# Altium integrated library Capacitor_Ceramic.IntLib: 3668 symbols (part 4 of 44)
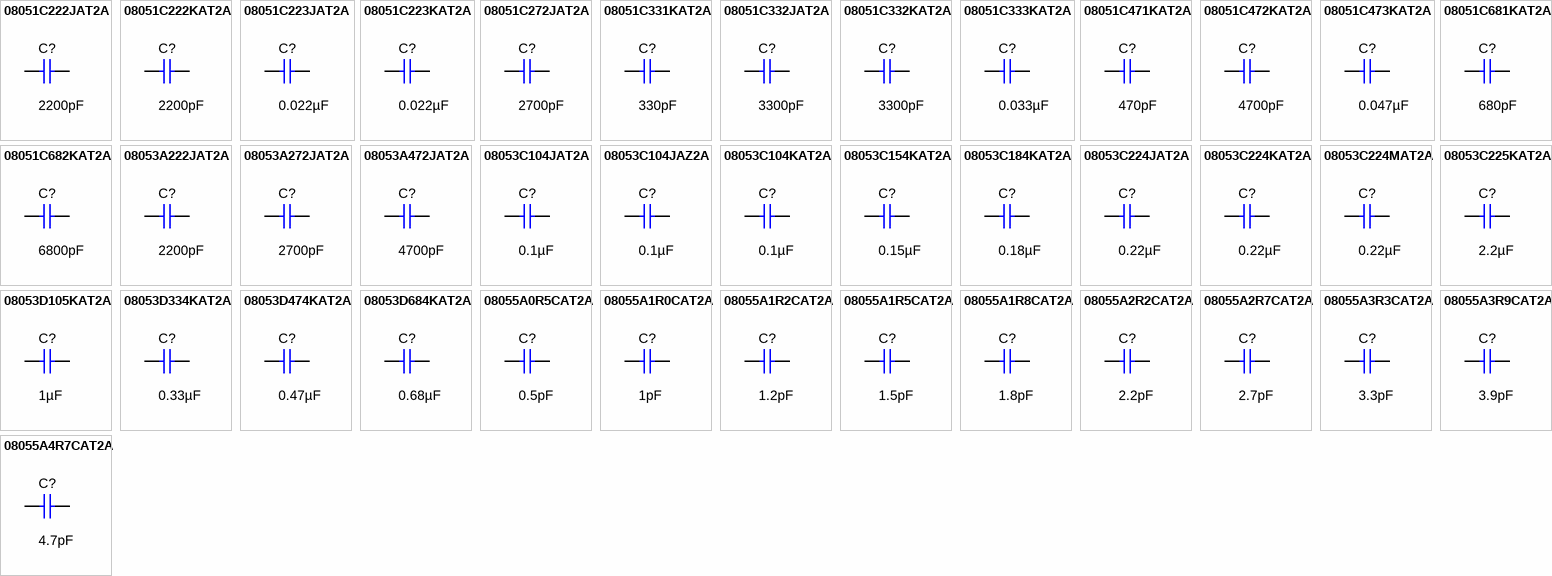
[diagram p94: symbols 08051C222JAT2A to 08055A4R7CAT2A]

## 08055A4R7CAT2A
designator C?  ValueDisplayed: 4.7pF  (hidden comment: 08055A4R7CAT2A)
CAP, CERM, 4.7 pF, 50 V,+/- 5%, C0G/NP0, 0805; Manufacturer: AVX; Polarized: N; CompType: Capacitor; Value: 4.7pF; U/M: EA; Cap_F: 0.0000000000047; Tolerance_%: 5; ESR_ohm: 2.668; Value1: 2.668 ohm; VDC_V: 50; Value2: 50V; TaMin_C: -55; TaMax_C: 125; Cap_Case: 0805; SizeArea_mm2: 2.5; SizeAreaWB_mm2: 6.75; SizeX_mm: 2; SizeY_mm: 1.25; SizeZ_mm: 1.45; AEC Category: Q200; Green_Lifecycle: Active; Green_REACh: Passed
signal-integrity model Cap
simulation model Cap
footprint 0805_HV
footprint 0805_HV1
footprint 0805
footprint 0805M
footprint 0805L
pins: 1, 2

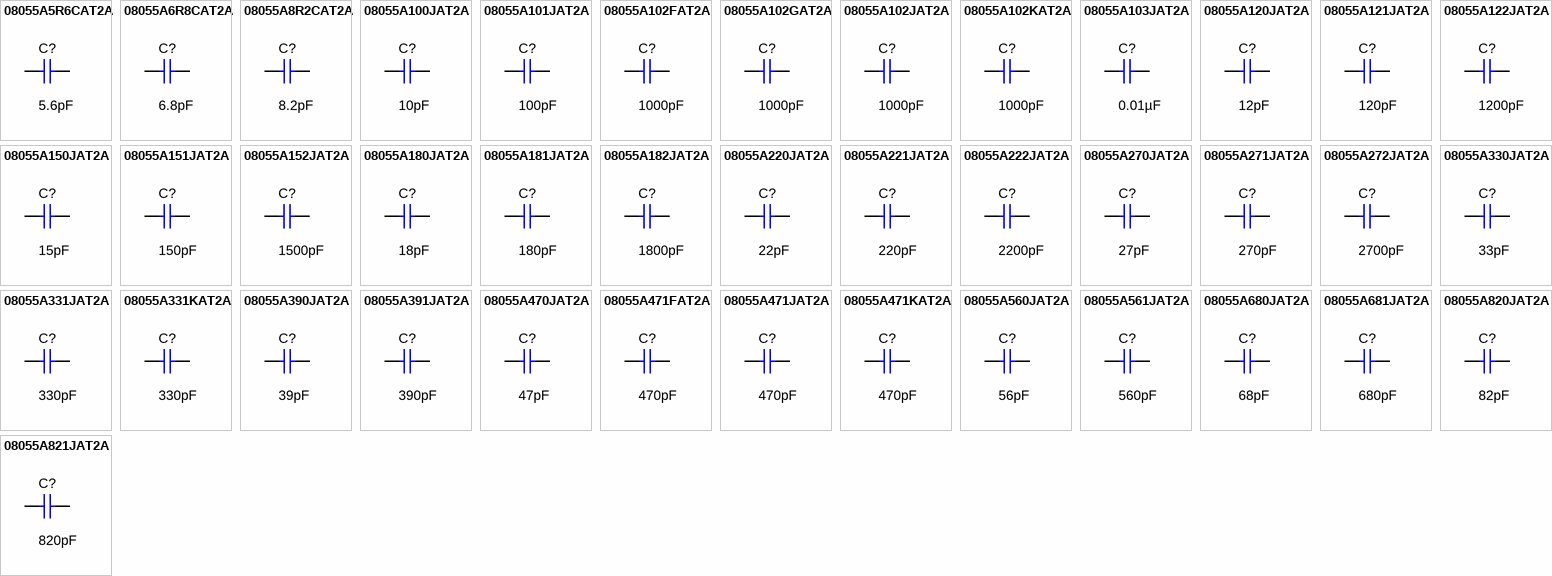
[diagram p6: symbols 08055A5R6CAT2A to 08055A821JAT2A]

## 08055A5R6CAT2A
designator C?  ValueDisplayed: 5.6pF  (hidden comment: 08055A5R6CAT2A)
CAP, CERM, 5.6 pF, 50 V,+/- 5%, C0G/NP0, 0805; Manufacturer: AVX; Polarized: N; CompType: Capacitor; Value: 5.6pF; U/M: EA; Cap_F: 0.0000000000056; Tolerance_%: 5; ESR_ohm: 2.349; Value1: 2.349 ohm; VDC_V: 50; Value2: 50V; TaMin_C: -55; TaMax_C: 125; Cap_Case: 0805; SizeArea_mm2: 2.5; SizeAreaWB_mm2: 6.75; SizeX_mm: 2; SizeY_mm: 1.25; SizeZ_mm: 1.45; AEC Category: Q200; Green_Lifecycle: Not Set; Green_REACh: Incomplete
signal-integrity model Cap
simulation model Cap
footprint 0805_HV
footprint 0805_HV1
footprint 0805
footprint 0805M
footprint 0805L
pins: 1, 2

## 08055A6R8CAT2A
designator C?  ValueDisplayed: 6.8pF  (hidden comment: 08055A6R8CAT2A)
CAP, CERM, 6.8 pF, 50 V,+/- 4%, C0G/NP0, 0805; Manufacturer: AVX; Polarized: N; CompType: Capacitor; Value: 6.8pF; U/M: EA; Cap_F: 0.0000000000068; Tolerance_%: 4; ESR_ohm: 2.045; Value1: 2.045 ohm; VDC_V: 50; Value2: 50V; TaMin_C: -55; TaMax_C: 125; Cap_Case: 0805; SizeArea_mm2: 2.5; SizeAreaWB_mm2: 6.75; SizeX_mm: 2; SizeY_mm: 1.25; SizeZ_mm: 1.45; AEC Category: Q200; Green_Lifecycle: Not Set; Green_REACh: Incomplete
signal-integrity model Cap
simulation model Cap
footprint 0805_HV
footprint 0805_HV1
footprint 0805
footprint 0805M
footprint 0805L
pins: 1, 2

## 08055A8R2CAT2A
designator C?  ValueDisplayed: 8.2pF  (hidden comment: 08055A8R2CAT2A)
CAP, CERM, 8.2 pF, 50 V,+/- 3%, C0G/NP0, 0805; Manufacturer: AVX; Polarized: N; CompType: Capacitor; Value: 8.2pF; U/M: EA; Cap_F: 0.0000000000082; Tolerance_%: 3; ESR_ohm: 1.792; Value1: 1.792 ohm; VDC_V: 50; Value2: 50V; TaMin_C: -55; TaMax_C: 125; Cap_Case: 0805; SizeArea_mm2: 2.5; SizeAreaWB_mm2: 6.75; SizeX_mm: 2; SizeY_mm: 1.25; SizeZ_mm: 1.45; AEC Category: Q200; Green_Lifecycle: Not Set; Green_REACh: Incomplete
signal-integrity model Cap
simulation model Cap
footprint 0805_HV
footprint 0805_HV1
footprint 0805
footprint 0805M
footprint 0805L
pins: 1, 2

## 08055A100JAT2A
designator C?  ValueDisplayed: 10pF  (hidden comment: 08055A100JAT2A)
CAP, CERM, 10 pF, 50 V,+/- 5%, C0G/NP0, 0805; Manufacturer: AVX; Polarized: N; CompType: Capacitor; Value: 10pF; U/M: EA; Cap_F: 0.00000000001; Tolerance_%: 5; ESR_ohm: 1.561; Value1: 1.561 ohm; VDC_V: 50; Value2: 50V; TaMin_C: -55; TaMax_C: 125; Cap_Case: 0805; SizeArea_mm2: 2.5; SizeAreaWB_mm2: 6.75; SizeX_mm: 2; SizeY_mm: 1.25; SizeZ_mm: 1.45; AEC Category: Q200; Green_Lifecycle: Active; Green_REACh: Passed
signal-integrity model Cap
simulation model Cap
footprint 0805_HV
footprint 0805_HV1
footprint 0805
footprint 0805M
footprint 0805L
pins: 1, 2

## 08055A101JAT2A
designator C?  ValueDisplayed: 100pF  (hidden comment: 08055A101JAT2A)
CAP, CERM, 100 pF, 50 V,+/- 5%, C0G/NP0, 0805; Manufacturer: AVX; Polarized: N; CompType: Capacitor; Value: 100pF; U/M: EA; Cap_F: 0.0000000001; Tolerance_%: 5; ESR_ohm: 0.356; Value1: 0.356 ohm; VDC_V: 50; Value2: 50V; TaMin_C: -55; TaMax_C: 125; Cap_Case: 0805; SizeArea_mm2: 2.5; SizeAreaWB_mm2: 6.75; SizeX_mm: 2; SizeY_mm: 1.25; SizeZ_mm: 1.45; AEC Category: Q200; Green_Lifecycle: Active; Green_REACh: Passed
signal-integrity model Cap
simulation model Cap
footprint 0805_HV
footprint 0805_HV1
footprint 0805
footprint 0805M
footprint 0805L
pins: 1, 2

## 08055A102FAT2A
designator C?  ValueDisplayed: 1000pF  (hidden comment: 08055A102FAT2A)
CAP, CERM, 1000 pF, 50 V,+/- 1%, C0G/NP0, 0805; Manufacturer: AVX; Polarized: N; CompType: Capacitor; Value: 1000pF; U/M: EA; Cap_F: 0.000000001; Tolerance_%: 1; ESR_ohm: 0.112; Value1: 0.112 ohm; VDC_V: 50; Value2: 50V; TaMin_C: -55; TaMax_C: 125; Cap_Case: 0805; SizeArea_mm2: 2.5; SizeAreaWB_mm2: 6.75; SizeX_mm: 2; SizeY_mm: 1.25; SizeZ_mm: 1.45; AEC Category: Q200; Green_Lifecycle: Active; Green_REACh: Passed
signal-integrity model Cap
simulation model Cap
footprint 0805_HV
footprint 0805_HV1
footprint 0805
footprint 0805M
footprint 0805L
pins: 1, 2

## 08055A102GAT2A
designator C?  ValueDisplayed: 1000pF  (hidden comment: 08055A102GAT2A)
CAP, CERM, 1000 pF, 50 V,+/- 2%, C0G/NP0, 0805; Manufacturer: AVX; Polarized: N; CompType: Capacitor; Value: 1000pF; U/M: EA; Cap_F: 0.000000001; Tolerance_%: 2; ESR_ohm: 0.112; Value1: 0.112 ohm; VDC_V: 50; Value2: 50V; TaMin_C: -55; TaMax_C: 125; Cap_Case: 0805; SizeArea_mm2: 2.5; SizeAreaWB_mm2: 6.75; SizeY_mm: 1.25; SizeZ_mm: 1.45; AEC Category: Q200; Green_Lifecycle: Not Set; Green_REACh: Incomplete
signal-integrity model Cap
simulation model Cap
footprint 0805_HV
footprint 0805_HV1
footprint 0805
footprint 0805M
footprint 0805L
pins: 1, 2

## 08055A102JAT2A
designator C?  ValueDisplayed: 1000pF  (hidden comment: 08055A102JAT2A)
CAP, CERM, 1000 pF, 50 V,+/- 5%, C0G/NP0, 0805; Manufacturer: AVX; Polarized: N; CompType: Capacitor; Value: 1000pF; U/M: EA; Cap_F: 0.000000001; Tolerance_%: 5; ESR_ohm: 0.112; Value1: 0.112 ohm; VDC_V: 50; Value2: 50V; TaMin_C: -55; TaMax_C: 125; Cap_Case: 0805; SizeArea_mm2: 2.5; SizeAreaWB_mm2: 6.75; SizeX_mm: 2; SizeY_mm: 1.25; SizeZ_mm: 1.45; AEC Category: Q200; Green_Lifecycle: Not Set; Green_REACh: Incomplete
signal-integrity model Cap
simulation model Cap
footprint 0805_HV
footprint 0805_HV1
footprint 0805
footprint 0805M
footprint 0805L
pins: 1, 2

## 08055A102KAT2A
designator C?  ValueDisplayed: 1000pF  (hidden comment: 08055A102KAT2A)
CAP, CERM, 1000 pF, 50 V,+/- 10%, C0G/NP0, 0805; Manufacturer: AVX; Polarized: N; CompType: Capacitor; Value: 1000pF; U/M: EA; Cap_F: 0.000000001; Tolerance_%: 10; ESR_ohm: 0.112; Value1: 0.112 ohm; VDC_V: 50; Value2: 50V; TaMin_C: -55; TaMax_C: 125; Cap_Case: 0805; SizeArea_mm2: 2.5; SizeAreaWB_mm2: 6.75; SizeX_mm: 2; SizeY_mm: 1.25; SizeZ_mm: 1.45; AEC Category: Q200; Green_Lifecycle: Not Set; Green_REACh: Incomplete
signal-integrity model Cap
simulation model Cap
footprint 0805_HV
footprint 0805_HV1
footprint 0805
footprint 0805M
footprint 0805L
pins: 1, 2

## 08055A103JAT2A
designator C?  ValueDisplayed: 0.01µF  (hidden comment: 08055A103JAT2A)
CAP, CERM, 0.01 µF, 50 V,+/- 5%, C0G/NP0, 0805; Manufacturer: AVX; Polarized: N; CompType: Capacitor; Value: 0.01uF; U/M: EA; Cap_F: 0.00000001; Tolerance_%: 5; VDC_V: 50; Value2: 50V; TaMin_C: -55; TaMax_C: 125; Cap_Case: 0805; SizeArea_mm2: 2.5; SizeAreaWB_mm2: 6.75; SizeX_mm: 2; SizeY_mm: 1.25; SizeZ_mm: 1.5; AEC Category: Q200
signal-integrity model Cap
simulation model Cap
footprint 0805_150
pins: 1, 2

## 08055A120JAT2A
designator C?  ValueDisplayed: 12pF  (hidden comment: 08055A120JAT2A)
CAP, CERM, 12 pF, 50 V,+/- 5%, C0G/NP0, 0805; Manufacturer: AVX; Polarized: N; CompType: Capacitor; Value: 12pF; U/M: EA; Cap_F: 0.000000000012; Tolerance_%: 5; ESR_ohm: 1.378; Value1: 1.378 ohm; VDC_V: 50; Value2: 50V; TaMin_C: -55; TaMax_C: 125; Cap_Case: 0805; SizeArea_mm2: 2.5; SizeAreaWB_mm2: 6.75; SizeX_mm: 2; SizeY_mm: 1.25; SizeZ_mm: 1.45; AEC Category: Q200; Green_Lifecycle: Not Set; Green_REACh: Incomplete
signal-integrity model Cap
simulation model Cap
footprint 0805_HV
footprint 0805_HV1
footprint 0805
footprint 0805M
footprint 0805L
pins: 1, 2

## 08055A121JAT2A
designator C?  ValueDisplayed: 120pF  (hidden comment: 08055A121JAT2A)
CAP, CERM, 120 pF, 50 V,+/- 5%, C0G/NP0, 0805; Manufacturer: AVX; Polarized: N; CompType: Capacitor; Value: 120pF; U/M: EA; Cap_F: 0.00000000012; Tolerance_%: 5; ESR_ohm: 0.319; Value1: 0.319 ohm; VDC_V: 50; Value2: 50V; TaMin_C: -55; TaMax_C: 125; Cap_Case: 0805; SizeArea_mm2: 2.5; SizeAreaWB_mm2: 6.75; SizeX_mm: 2; SizeY_mm: 1.25; SizeZ_mm: 1.45; AEC Category: Q200; Green_Lifecycle: Not Set; Green_REACh: Incomplete
signal-integrity model Cap
simulation model Cap
footprint 0805_HV
footprint 0805_HV1
footprint 0805
footprint 0805M
footprint 0805L
pins: 1, 2

## 08055A122JAT2A
designator C?  ValueDisplayed: 1200pF  (hidden comment: 08055A122JAT2A)
CAP, CERM, 1200 pF, 50 V,+/- 5%, C0G/NP0, 0805; Manufacturer: AVX; Polarized: N; CompType: Capacitor; Value: 1200pF; U/M: EA; Cap_F: 0.0000000012; Tolerance_%: 5; ESR_ohm: 0.104; Value1: 0.104 ohm; VDC_V: 50; Value2: 50V; TaMin_C: -55; TaMax_C: 125; Cap_Case: 0805; SizeArea_mm2: 2.5; SizeAreaWB_mm2: 6.75; SizeX_mm: 2; SizeY_mm: 1.25; SizeZ_mm: 1.45; AEC Category: Q200; Green_Lifecycle: Active; Green_REACh: Passed
signal-integrity model Cap
simulation model Cap
footprint 0805_HV
footprint 0805_HV1
footprint 0805
footprint 0805M
footprint 0805L
pins: 1, 2

## 08055A150JAT2A
designator C?  ValueDisplayed: 15pF  (hidden comment: 08055A150JAT2A)
CAP, CERM, 15 pF, 50 V,+/- 5%, C0G/NP0, 0805; Manufacturer: AVX; Polarized: N; CompType: Capacitor; Value: 15pF; U/M: EA; Cap_F: 0.000000000015; Tolerance_%: 5; ESR_ohm: 1.185; Value1: 1.185 ohm; VDC_V: 50; Value2: 50V; TaMin_C: -55; TaMax_C: 125; Cap_Case: 0805; SizeArea_mm2: 2.5; SizeAreaWB_mm2: 6.75; SizeX_mm: 2; SizeY_mm: 1.25; SizeZ_mm: 1.45; AEC Category: Q200; Green_Lifecycle: Not Set; Green_REACh: Incomplete
signal-integrity model Cap
simulation model Cap
footprint 0805_HV
footprint 0805_HV1
footprint 0805
footprint 0805M
footprint 0805L
pins: 1, 2

## 08055A151JAT2A
designator C?  ValueDisplayed: 150pF  (hidden comment: 08055A151JAT2A)
CAP, CERM, 150 pF, 50 V,+/- 5%, C0G/NP0, 0805; Manufacturer: AVX; Polarized: N; CompType: Capacitor; Value: 150pF; U/M: EA; Cap_F: 0.00000000015; Tolerance_%: 5; ESR_ohm: 0.279; Value1: 0.279 ohm; VDC_V: 50; Value2: 50V; TaMin_C: -55; TaMax_C: 125; Cap_Case: 0805; SizeArea_mm2: 2.5; SizeAreaWB_mm2: 6.75; SizeX_mm: 2; SizeY_mm: 1.25; SizeZ_mm: 1.45; AEC Category: Q200; Green_Lifecycle: Not Set; Green_REACh: Incomplete
signal-integrity model Cap
simulation model Cap
footprint 0805_HV
footprint 0805_HV1
footprint 0805
footprint 0805M
footprint 0805L
pins: 1, 2

## 08055A152JAT2A
designator C?  ValueDisplayed: 1500pF  (hidden comment: 08055A152JAT2A)
CAP, CERM, 1500 pF, 50 V,+/- 5%, C0G/NP0, 0805; Manufacturer: AVX; Polarized: N; CompType: Capacitor; Value: 1500pF; U/M: EA; Cap_F: 0.0000000015; Tolerance_%: 5; ESR_ohm: 0.094; Value1: 0.094 ohm; VDC_V: 50; Value2: 50V; TaMin_C: -55; TaMax_C: 125; Cap_Case: 0805; SizeArea_mm2: 2.5; SizeAreaWB_mm2: 6.75; SizeX_mm: 2; SizeY_mm: 1.25; SizeZ_mm: 1.45; AEC Category: Q200; Green_Lifecycle: Not Set; Green_REACh: Incomplete
signal-integrity model Cap
simulation model Cap
footprint 0805_HV
footprint 0805_HV1
footprint 0805
footprint 0805M
footprint 0805L
pins: 1, 2

## 08055A180JAT2A
designator C?  ValueDisplayed: 18pF  (hidden comment: 08055A180JAT2A)
CAP, CERM, 18 pF, 50 V,+/- 5%, C0G/NP0, 0805; Manufacturer: AVX; Polarized: N; CompType: Capacitor; Value: 18pF; U/M: EA; Cap_F: 0.000000000018; Tolerance_%: 5; ESR_ohm: 1.049; Value1: 1.049 ohm; VDC_V: 50; Value2: 50V; TaMin_C: -55; TaMax_C: 125; Cap_Case: 0805; SizeArea_mm2: 2.5; SizeAreaWB_mm2: 6.75; SizeX_mm: 2; SizeY_mm: 1.25; SizeZ_mm: 1.45; AEC Category: Q200; Green_Lifecycle: Not Set; Green_REACh: Incomplete
signal-integrity model Cap
simulation model Cap
footprint 0805_HV
footprint 0805_HV1
footprint 0805
footprint 0805M
footprint 0805L
pins: 1, 2

## 08055A181JAT2A
designator C?  ValueDisplayed: 180pF  (hidden comment: 08055A181JAT2A)
CAP, CERM, 180 pF, 50 V,+/- 5%, C0G/NP0, 0805; Manufacturer: AVX; Polarized: N; CompType: Capacitor; Value: 180pF; U/M: EA; Cap_F: 0.00000000018; Tolerance_%: 5; ESR_ohm: 0.255; Value1: 0.255 ohm; VDC_V: 50; Value2: 50V; TaMin_C: -55; TaMax_C: 125; Cap_Case: 0805; SizeArea_mm2: 2.5; SizeAreaWB_mm2: 6.75; SizeX_mm: 2; SizeY_mm: 1.25; SizeZ_mm: 1.45; AEC Category: Q200; Green_Lifecycle: Not Set; Green_REACh: Incomplete
signal-integrity model Cap
simulation model Cap
footprint 0805_HV
footprint 0805_HV1
footprint 0805
footprint 0805M
footprint 0805L
pins: 1, 2

## 08055A182JAT2A
designator C?  ValueDisplayed: 1800pF  (hidden comment: 08055A182JAT2A)
CAP, CERM, 1800 pF, 50 V,+/- 5%, C0G/NP0, 0805; Manufacturer: AVX; Polarized: N; CompType: Capacitor; Value: 1800pF; U/M: EA; Cap_F: 0.0000000018; Tolerance_%: 5; ESR_ohm: 0.087; Value1: 0.087 ohm; VDC_V: 50; Value2: 50V; TaMin_C: -55; TaMax_C: 125; Cap_Case: 0805; SizeArea_mm2: 2.5; SizeAreaWB_mm2: 6.75; SizeX_mm: 2; SizeY_mm: 1.25; SizeZ_mm: 1.45; AEC Category: Q200; Green_Lifecycle: Not Set; Green_REACh: Incomplete
signal-integrity model Cap
simulation model Cap
footprint 0805_HV
footprint 0805_HV1
footprint 0805
footprint 0805M
footprint 0805L
pins: 1, 2

## 08055A220JAT2A
designator C?  ValueDisplayed: 22pF  (hidden comment: 08055A220JAT2A)
CAP, CERM, 22 pF, 50 V,+/- 5%, C0G/NP0, 0805; Manufacturer: AVX; Polarized: N; CompType: Capacitor; Value: 22pF; U/M: EA; Cap_F: 0.000000000022; Tolerance_%: 5; ESR_ohm: 0.92; Value1: 0.92 ohm; VDC_V: 50; Value2: 50V; TaMin_C: -55; TaMax_C: 125; Cap_Case: 0805; SizeArea_mm2: 2.5; SizeAreaWB_mm2: 6.75; SizeX_mm: 2; SizeY_mm: 1.25; SizeZ_mm: 1.45; AEC Category: Q200; Green_Lifecycle: Active; Green_REACh: Passed
signal-integrity model Cap
simulation model Cap
footprint 0805_HV
footprint 0805_HV1
footprint 0805
footprint 0805M
footprint 0805L
pins: 1, 2

## 08055A221JAT2A
designator C?  ValueDisplayed: 220pF  (hidden comment: 08055A221JAT2A)
CAP, CERM, 220 pF, 50 V,+/- 5%, C0G/NP0, 0805; Manufacturer: AVX; Polarized: N; CompType: Capacitor; Value: 220pF; U/M: EA; Cap_F: 0.00000000022; Tolerance_%: 5; ESR_ohm: 0.23; Value1: 0.23 ohm; VDC_V: 50; Value2: 50V; TaMin_C: -55; TaMax_C: 125; Cap_Case: 0805; SizeArea_mm2: 2.5; SizeAreaWB_mm2: 6.75; SizeX_mm: 2; SizeY_mm: 1.25; SizeZ_mm: 1.45; AEC Category: Q200; Green_Lifecycle: Not Set; Green_REACh: Incomplete
signal-integrity model Cap
simulation model Cap
footprint 0805_HV
footprint 0805_HV1
footprint 0805
footprint 0805M
footprint 0805L
pins: 1, 2

## 08055A222JAT2A
designator C?  ValueDisplayed: 2200pF  (hidden comment: 08055A222JAT2A)
CAP, CERM, 2200 pF, 50 V,+/- 5%, C0G/NP0, 0805; Manufacturer: AVX; Polarized: N; CompType: Capacitor; Value: 2200pF; U/M: EA; Cap_F: 0.0000000022; Tolerance_%: 5; ESR_ohm: 0.08; Value1: 0.08 ohm; VDC_V: 50; Value2: 50V; TaMin_C: -55; TaMax_C: 125; Cap_Case: 0805; SizeArea_mm2: 2.5; SizeAreaWB_mm2: 6.75; SizeX_mm: 2; SizeY_mm: 1.25; SizeZ_mm: 1.45; AEC Category: Q200; Green_Lifecycle: Not Set; Green_REACh: Incomplete
signal-integrity model Cap
simulation model Cap
footprint 0805_HV
footprint 0805_HV1
footprint 0805
footprint 0805M
footprint 0805L
pins: 1, 2

## 08055A270JAT2A
designator C?  ValueDisplayed: 27pF  (hidden comment: 08055A270JAT2A)
CAP, CERM, 27 pF, 50 V,+/- 5%, C0G/NP0, 0805; Manufacturer: AVX; Polarized: N; CompType: Capacitor; Value: 27pF; U/M: EA; Cap_F: 0.000000000027; Tolerance_%: 5; ESR_ohm: 0.805; Value1: 0.805 ohm; VDC_V: 50; Value2: 50V; TaMin_C: -55; TaMax_C: 125; Cap_Case: 0805; SizeArea_mm2: 2.5; SizeAreaWB_mm2: 6.75; SizeX_mm: 2; SizeY_mm: 1.25; SizeZ_mm: 1.45; AEC Category: Q200; Green_Lifecycle: Not Set; Green_REACh: Incomplete
signal-integrity model Cap
simulation model Cap
footprint 0805_HV
footprint 0805_HV1
footprint 0805
footprint 0805M
footprint 0805L
pins: 1, 2

## 08055A271JAT2A
designator C?  ValueDisplayed: 270pF  (hidden comment: 08055A271JAT2A)
CAP, CERM, 270 pF, 50 V,+/- 5%, C0G/NP0, 0805; Manufacturer: AVX; Polarized: N; CompType: Capacitor; Value: 270pF; U/M: EA; Cap_F: 0.00000000027; Tolerance_%: 5; ESR_ohm: 0.208; Value1: 0.208 ohm; VDC_V: 50; Value2: 50V; TaMin_C: -55; TaMax_C: 125; Cap_Case: 0805; SizeArea_mm2: 2.5; SizeAreaWB_mm2: 6.75; SizeX_mm: 2; SizeY_mm: 1.25; SizeZ_mm: 1.45; AEC Category: Q200; Green_Lifecycle: Not Set; Green_REACh: Incomplete
signal-integrity model Cap
simulation model Cap
footprint 0805_HV
footprint 0805_HV1
footprint 0805
footprint 0805M
footprint 0805L
pins: 1, 2

## 08055A272JAT2A
designator C?  ValueDisplayed: 2700pF  (hidden comment: 08055A272JAT2A)
CAP, CERM, 2700 pF, 50 V,+/- 5%, C0G/NP0, 0805; Manufacturer: AVX; Polarized: N; CompType: Capacitor; Value: 2700pF; U/M: EA; Cap_F: 0.0000000027; Tolerance_%: 5; ESR_ohm: 0.074; Value1: 0.074 ohm; VDC_V: 50; Value2: 50V; TaMin_C: -55; TaMax_C: 125; Cap_Case: 0805; SizeArea_mm2: 2.5; SizeAreaWB_mm2: 6.75; SizeX_mm: 2; SizeY_mm: 1.25; SizeZ_mm: 1.45; AEC Category: Q200; Green_Lifecycle: Active; Green_REACh: Passed
signal-integrity model Cap
simulation model Cap
footprint 0805_HV
footprint 0805_HV1
footprint 0805
footprint 0805M
footprint 0805L
pins: 1, 2

## 08055A330JAT2A
designator C?  ValueDisplayed: 33pF  (hidden comment: 08055A330JAT2A)
CAP, CERM, 33 pF, 50 V,+/- 5%, C0G/NP0, 0805; Manufacturer: AVX; Polarized: N; CompType: Capacitor; Value: 33pF; U/M: EA; Cap_F: 0.000000000033; Tolerance_%: 5; ESR_ohm: 0.708; Value1: 0.708 ohm; VDC_V: 50; Value2: 50V; TaMin_C: -55; TaMax_C: 125; Cap_Case: 0805; SizeArea_mm2: 2.5; SizeAreaWB_mm2: 6.75; SizeX_mm: 2; SizeY_mm: 1.25; SizeZ_mm: 1.45; AEC Category: Q200; Green_Lifecycle: Not Set; Green_REACh: Incomplete
signal-integrity model Cap
simulation model Cap
footprint 0805_HV
footprint 0805_HV1
footprint 0805
footprint 0805M
footprint 0805L
pins: 1, 2

## 08055A331JAT2A
designator C?  ValueDisplayed: 330pF  (hidden comment: 08055A331JAT2A)
CAP, CERM, 330 pF, 50 V,+/- 5%, C0G/NP0, 0805; Manufacturer: AVX; Polarized: N; CompType: Capacitor; Value: 330pF; U/M: EA; Cap_F: 0.00000000033; Tolerance_%: 5; ESR_ohm: 0.189; Value1: 0.189 ohm; VDC_V: 50; Value2: 50V; TaMin_C: -55; TaMax_C: 125; Cap_Case: 0805; SizeArea_mm2: 2.5; SizeAreaWB_mm2: 6.75; SizeX_mm: 2; SizeY_mm: 1.25; SizeZ_mm: 1.45; AEC Category: Q200; Green_Lifecycle: Active; Green_REACh: Passed
signal-integrity model Cap
simulation model Cap
footprint 0805_HV
footprint 0805_HV1
footprint 0805
footprint 0805M
footprint 0805L
pins: 1, 2

## 08055A331KAT2A
designator C?  ValueDisplayed: 330pF  (hidden comment: 08055A331KAT2A)
CAP, CERM, 330 pF, 50 V,+/- 10%, C0G/NP0, 0805; Manufacturer: AVX; Polarized: N; CompType: Capacitor; Value: 330pF; U/M: EA; Cap_F: 0.00000000033; Tolerance_%: 10; ESR_ohm: 0.189; Value1: 0.189 ohm; VDC_V: 50; Value2: 50V; TaMin_C: -55; TaMax_C: 125; Cap_Case: 0805; SizeArea_mm2: 2.5; SizeAreaWB_mm2: 6.75; SizeX_mm: 2; SizeY_mm: 1.25; SizeZ_mm: 1.45; AEC Category: Q200; Green_Lifecycle: Not Set; Green_REACh: Incomplete
signal-integrity model Cap
simulation model Cap
footprint 0805_HV
footprint 0805_HV1
footprint 0805
footprint 0805M
footprint 0805L
pins: 1, 2

## 08055A390JAT2A
designator C?  ValueDisplayed: 39pF  (hidden comment: 08055A390JAT2A)
CAP, CERM, 39 pF, 50 V,+/- 5%, C0G/NP0, 0805; Manufacturer: AVX; Polarized: N; CompType: Capacitor; Value: 39pF; U/M: EA; Cap_F: 0.000000000039; Tolerance_%: 5; ESR_ohm: 0.637; Value1: 0.637 ohm; VDC_V: 50; Value2: 50V; TaMin_C: -55; TaMax_C: 125; Cap_Case: 0805; SizeArea_mm2: 2.5; SizeAreaWB_mm2: 6.75; SizeX_mm: 2; SizeY_mm: 1.25; SizeZ_mm: 1.45; AEC Category: Q200; Green_Lifecycle: Not Set; Green_REACh: Incomplete
signal-integrity model Cap
simulation model Cap
footprint 0805_HV
footprint 0805_HV1
footprint 0805
footprint 0805M
footprint 0805L
pins: 1, 2

## 08055A391JAT2A
designator C?  ValueDisplayed: 390pF  (hidden comment: 08055A391JAT2A)
CAP, CERM, 390 pF, 50 V,+/- 5%, C0G/NP0, 0805; Manufacturer: AVX; Polarized: N; CompType: Capacitor; Value: 390pF; U/M: EA; Cap_F: 0.00000000039; Tolerance_%: 5; ESR_ohm: 0.174; Value1: 0.174 ohm; VDC_V: 50; Value2: 50V; TaMin_C: -55; TaMax_C: 125; Cap_Case: 0805; SizeArea_mm2: 2.5; SizeAreaWB_mm2: 6.75; SizeX_mm: 2; SizeY_mm: 1.25; SizeZ_mm: 1.45; AEC Category: Q200; Green_Lifecycle: Active; Green_REACh: Passed
signal-integrity model Cap
simulation model Cap
footprint 0805_HV
footprint 0805_HV1
footprint 0805
footprint 0805M
footprint 0805L
pins: 1, 2

## 08055A470JAT2A
designator C?  ValueDisplayed: 47pF  (hidden comment: 08055A470JAT2A)
CAP, CERM, 47 pF, 50 V,+/- 5%, C0G/NP0, 0805; Manufacturer: AVX; Polarized: N; CompType: Capacitor; Value: 47pF; U/M: EA; Cap_F: 0.000000000047; Tolerance_%: 5; ESR_ohm: 0.566; Value1: 0.566 ohm; VDC_V: 50; Value2: 50V; TaMin_C: -55; TaMax_C: 125; Cap_Case: 0805; SizeArea_mm2: 2.5; SizeAreaWB_mm2: 6.75; SizeX_mm: 2; SizeY_mm: 1.25; SizeZ_mm: 1.45; AEC Category: Q200; Green_Lifecycle: Active; Green_REACh: Passed
signal-integrity model Cap
simulation model Cap
footprint 0805_HV
footprint 0805_HV1
footprint 0805
footprint 0805M
footprint 0805L
pins: 1, 2

## 08055A471FAT2A
designator C?  ValueDisplayed: 470pF  (hidden comment: 08055A471FAT2A)
CAP, CERM, 470 pF, 50 V,+/- 1%, C0G/NP0, 0805; Manufacturer: AVX; Polarized: N; CompType: Capacitor; Value: 470pF; U/M: EA; Cap_F: 0.00000000047; Tolerance_%: 1; ESR_ohm: 0.159; Value1: 0.159 ohm; VDC_V: 50; Value2: 50V; TaMin_C: -55; TaMax_C: 125; Cap_Case: 0805; SizeArea_mm2: 2.5; SizeAreaWB_mm2: 6.75; SizeX_mm: 2; SizeY_mm: 1.25; SizeZ_mm: 1.45; AEC Category: Q200; Green_Lifecycle: Active; Green_REACh: Passed
signal-integrity model Cap
simulation model Cap
footprint 0805_HV
footprint 0805_HV1
footprint 0805
footprint 0805M
footprint 0805L
pins: 1, 2

## 08055A471JAT2A
designator C?  ValueDisplayed: 470pF  (hidden comment: 08055A471JAT2A)
CAP, CERM, 470 pF, 50 V,+/- 5%, C0G/NP0, 0805; Manufacturer: AVX; Polarized: N; CompType: Capacitor; Value: 470pF; U/M: EA; Cap_F: 0.00000000047; Tolerance_%: 5; ESR_ohm: 0.159; Value1: 0.159 ohm; VDC_V: 50; Value2: 50V; TaMin_C: -55; TaMax_C: 125; Cap_Case: 0805; SizeArea_mm2: 2.5; SizeAreaWB_mm2: 6.75; SizeX_mm: 2; SizeY_mm: 1.25; SizeZ_mm: 1.45; AEC Category: Q200; Green_Lifecycle: Not Set; Green_REACh: Incomplete
signal-integrity model Cap
simulation model Cap
footprint 0805_HV
footprint 0805_HV1
footprint 0805
footprint 0805M
footprint 0805L
pins: 1, 2

## 08055A471KAT2A
designator C?  ValueDisplayed: 470pF  (hidden comment: 08055A471KAT2A)
CAP, CERM, 470 pF, 50 V,+/- 10%, C0G/NP0, 0805; Manufacturer: AVX; Polarized: N; CompType: Capacitor; Value: 470pF; U/M: EA; Cap_F: 0.00000000047; Tolerance_%: 10; ESR_ohm: 0.159; Value1: 0.159 ohm; VDC_V: 50; Value2: 50V; TaMin_C: -55; TaMax_C: 125; Cap_Case: 0805; SizeArea_mm2: 2.5; SizeAreaWB_mm2: 6.75; SizeX_mm: 2; SizeY_mm: 1.25; SizeZ_mm: 1.45; AEC Category: Q200; Green_Lifecycle: Not Set; Green_REACh: Incomplete
signal-integrity model Cap
simulation model Cap
footprint 0805_HV
footprint 0805_HV1
footprint 0805
footprint 0805M
footprint 0805L
pins: 1, 2

## 08055A560JAT2A
designator C?  ValueDisplayed: 56pF  (hidden comment: 08055A560JAT2A)
CAP, CERM, 56 pF, 50 V,+/- 5%, C0G/NP0, 0805; Manufacturer: AVX; Polarized: N; CompType: Capacitor; Value: 56pF; U/M: EA; Cap_F: 0.000000000056; Tolerance_%: 5; ESR_ohm: 0.508; Value1: 0.508 ohm; VDC_V: 50; Value2: 50V; TaMin_C: -55; TaMax_C: 125; Cap_Case: 0805; SizeArea_mm2: 2.5; SizeAreaWB_mm2: 6.75; SizeX_mm: 2; SizeY_mm: 1.25; SizeZ_mm: 1.45; AEC Category: Q200; Green_Lifecycle: Not Set; Green_REACh: Incomplete
signal-integrity model Cap
simulation model Cap
footprint 0805_HV
footprint 0805_HV1
footprint 0805
footprint 0805M
footprint 0805L
pins: 1, 2

## 08055A561JAT2A
designator C?  ValueDisplayed: 560pF  (hidden comment: 08055A561JAT2A)
CAP, CERM, 560 pF, 50 V,+/- 5%, C0G/NP0, 0805; Manufacturer: AVX; Polarized: N; CompType: Capacitor; Value: 560pF; U/M: EA; Cap_F: 0.00000000056; Tolerance_%: 5; ESR_ohm: 0.147; Value1: 0.147 ohm; VDC_V: 50; Value2: 50V; TaMin_C: -55; TaMax_C: 125; Cap_Case: 0805; SizeArea_mm2: 2.5; SizeAreaWB_mm2: 6.75; SizeX_mm: 2; SizeY_mm: 1.25; SizeZ_mm: 1.45; AEC Category: Q200; Green_Lifecycle: Active; Green_REACh: Passed
signal-integrity model Cap
simulation model Cap
footprint 0805_HV
footprint 0805_HV1
footprint 0805
footprint 0805M
footprint 0805L
pins: 1, 2

## 08055A680JAT2A
designator C?  ValueDisplayed: 68pF  (hidden comment: 08055A680JAT2A)
CAP, CERM, 68 pF, 50 V,+/- 5%, C0G/NP0, 0805; Manufacturer: AVX; Polarized: N; CompType: Capacitor; Value: 68pF; U/M: EA; Cap_F: 0.000000000068; Tolerance_%: 5; ESR_ohm: 0.45; Value1: 0.45 ohm; VDC_V: 50; Value2: 50V; TaMin_C: -55; TaMax_C: 125; Cap_Case: 0805; SizeArea_mm2: 2.5; SizeAreaWB_mm2: 6.75; SizeX_mm: 2; SizeY_mm: 1.25; SizeZ_mm: 1.45; AEC Category: Q200; Green_Lifecycle: Not Set; Green_REACh: Incomplete
signal-integrity model Cap
simulation model Cap
footprint 0805_HV
footprint 0805_HV1
footprint 0805
footprint 0805M
footprint 0805L
pins: 1, 2

## 08055A681JAT2A
designator C?  ValueDisplayed: 680pF  (hidden comment: 08055A681JAT2A)
CAP, CERM, 680 pF, 50 V,+/- 5%, C0G/NP0, 0805; Manufacturer: AVX; Polarized: N; CompType: Capacitor; Value: 680pF; U/M: EA; Cap_F: 0.00000000068; Tolerance_%: 5; ESR_ohm: 0.134; Value1: 0.134 ohm; VDC_V: 50; Value2: 50V; TaMin_C: -55; TaMax_C: 125; Cap_Case: 0805; SizeArea_mm2: 2.5; SizeAreaWB_mm2: 6.75; SizeX_mm: 2; SizeY_mm: 1.25; SizeZ_mm: 1.45; AEC Category: Q200; Green_Lifecycle: Not Set; Green_REACh: Incomplete
signal-integrity model Cap
simulation model Cap
footprint 0805_HV
footprint 0805_HV1
footprint 0805
footprint 0805M
footprint 0805L
pins: 1, 2

## 08055A820JAT2A
designator C?  ValueDisplayed: 82pF  (hidden comment: 08055A820JAT2A)
CAP, CERM, 82 pF, 50 V,+/- 5%, C0G/NP0, 0805; Manufacturer: AVX; Polarized: N; CompType: Capacitor; Value: 82pF; U/M: EA; Cap_F: 0.000000000082; Tolerance_%: 5; ESR_ohm: 0.401; Value1: 0.401 ohm; VDC_V: 50; Value2: 50V; TaMin_C: -55; TaMax_C: 125; Cap_Case: 0805; SizeArea_mm2: 2.5; SizeAreaWB_mm2: 6.75; SizeX_mm: 2; SizeY_mm: 1.25; SizeZ_mm: 1.45; AEC Category: Q200; Green_Lifecycle: Active; Green_REACh: Passed
signal-integrity model Cap
simulation model Cap
footprint 0805_HV
footprint 0805_HV1
footprint 0805
footprint 0805M
footprint 0805L
pins: 1, 2

## 08055A821JAT2A
designator C?  ValueDisplayed: 820pF  (hidden comment: 08055A821JAT2A)
CAP, CERM, 820 pF, 50 V,+/- 5%, C0G/NP0, 0805; Manufacturer: AVX; Polarized: N; CompType: Capacitor; Value: 820pF; U/M: EA; Cap_F: 0.00000000082; Tolerance_%: 5; ESR_ohm: 0.123; Value1: 0.123 ohm; VDC_V: 50; Value2: 50V; TaMin_C: -55; TaMax_C: 125; Cap_Case: 0805; SizeArea_mm2: 2.5; SizeAreaWB_mm2: 6.75; SizeX_mm: 2; SizeY_mm: 1.25; SizeZ_mm: 1.45; AEC Category: Q200; Green_Lifecycle: Not Set; Green_REACh: Incomplete
signal-integrity model Cap
simulation model Cap
footprint 0805_HV
footprint 0805_HV1
footprint 0805
footprint 0805M
footprint 0805L
pins: 1, 2

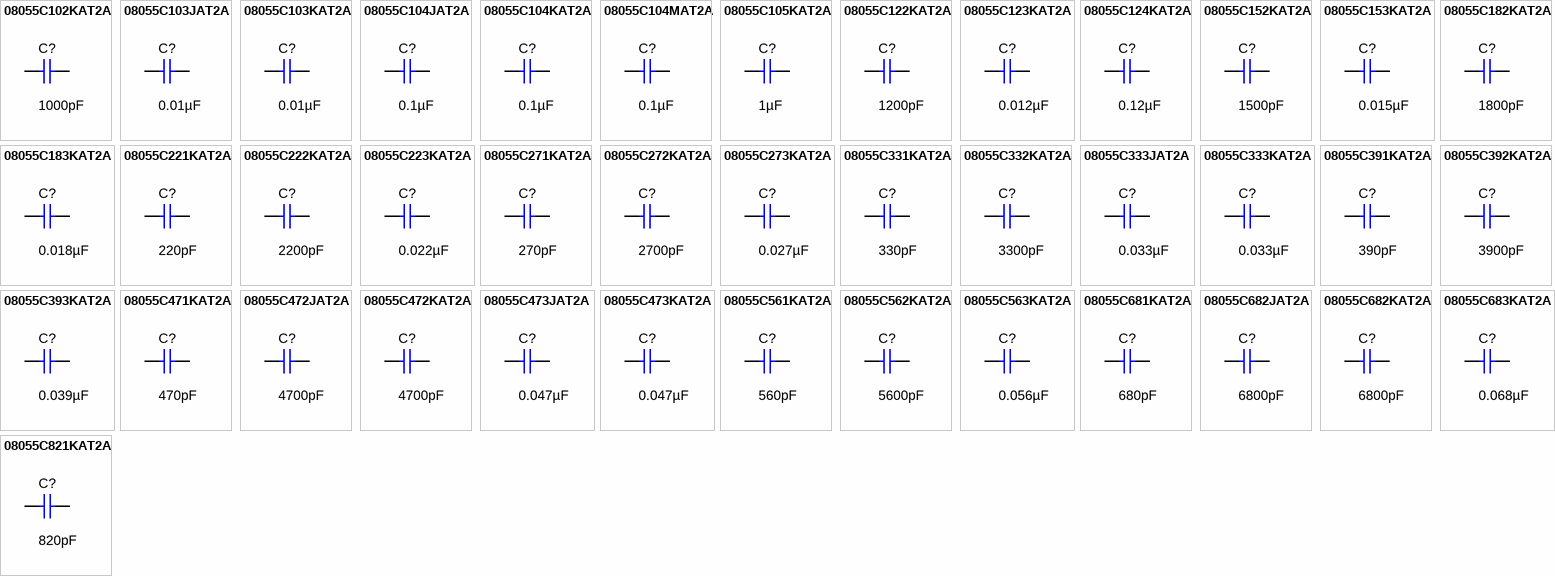
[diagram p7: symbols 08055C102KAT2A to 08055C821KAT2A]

## 08055C102KAT2A
designator C?  ValueDisplayed: 1000pF  (hidden comment: 08055C102KAT2A)
CAP, CERM, 1000 pF, 50 V,+/- 10%, X7R, 0805; Manufacturer: AVX; Polarized: N; CompType: Capacitor; Value: 1000pF; U/M: EA; Cap_F: 0.000000001; Tolerance_%: 10; ESR_ohm: 0.29; Value1: 0.29 ohm; VDC_V: 50; Value2: 50V; TaMin_C: -55; TaMax_C: 125; Cap_Case: 0805; SizeArea_mm2: 2.5; SizeAreaWB_mm2: 6.75; SizeX_mm: 2; SizeY_mm: 1.25; SizeZ_mm: 1.45; AEC Category: Q200; Green_Lifecycle: Active; Green_REACh: Passed
signal-integrity model Cap
simulation model Cap
footprint 0805_HV
footprint 0805_HV1
footprint 0805
footprint 0805M
footprint 0805L
pins: 1, 2

## 08055C103JAT2A
designator C?  ValueDisplayed: 0.01µF  (hidden comment: 08055C103JAT2A)
CAP, CERM, 0.01 µF, 50 V,+/- 5%, X7R, 0805; Manufacturer: AVX; Polarized: N; CompType: Capacitor; Value: 0.01uF; U/M: EA; Cap_F: 0.00000001; Tolerance_%: 5; ESR_ohm: 0.078; Value1: 0.078 ohm; VDC_V: 50; Value2: 50V; TaMin_C: -55; TaMax_C: 125; Cap_Case: 0805; SizeArea_mm2: 2.5; SizeAreaWB_mm2: 6.75; SizeX_mm: 2; SizeY_mm: 1.25; SizeZ_mm: 1.45; AEC Category: Q200; Green_Lifecycle: Active; Green_REACh: Passed
signal-integrity model Cap
simulation model Cap
footprint 0805_HV
footprint 0805_HV1
footprint 0805
footprint 0805M
footprint 0805L
pins: 1, 2

## 08055C103KAT2A
designator C?  ValueDisplayed: 0.01µF  (hidden comment: 08055C103KAT2A)
CAP, CERM, 0.01 µF, 50 V,+/- 10%, X7R, 0805; Manufacturer: AVX; Polarized: N; CompType: Capacitor; Value: 0.01uF; U/M: EA; Cap_F: 0.00000001; Tolerance_%: 10; ESR_ohm: 0.078; Value1: 0.078 ohm; VDC_V: 50; Value2: 50V; TaMin_C: -55; TaMax_C: 125; Cap_Case: 0805; SizeArea_mm2: 2.5; SizeAreaWB_mm2: 6.75; SizeX_mm: 2; SizeY_mm: 1.25; SizeZ_mm: 1.45; AEC Category: Q200; Green_Lifecycle: Active; Green_REACh: Passed
signal-integrity model Cap
simulation model Cap
footprint 0805_HV
footprint 0805_HV1
footprint 0805
footprint 0805M
footprint 0805L
pins: 1, 2

## 08055C104JAT2A
designator C?  ValueDisplayed: 0.1µF  (hidden comment: 08055C104JAT2A)
CAP, CERM, 0.1 µF, 50 V,+/- 5%, X7R, 0805; Manufacturer: AVX; Polarized: N; CompType: Capacitor; Value: 0.1uF; U/M: EA; Cap_F: 0.0000001; Tolerance_%: 5; ESR_ohm: 0.024; Value1: 0.024 ohm; VDC_V: 50; Value2: 50V; TaMin_C: -55; TaMax_C: 125; Cap_Case: 0805; SizeArea_mm2: 2.5; SizeAreaWB_mm2: 6.75; SizeX_mm: 2; SizeY_mm: 1.25; SizeZ_mm: 1.45; AEC Category: Q200; Green_Lifecycle: Active; Green_REACh: Passed
signal-integrity model Cap
simulation model Cap
footprint 0805_HV
footprint 0805_HV1
footprint 0805
footprint 0805M
footprint 0805L
pins: 1, 2

## 08055C104KAT2A
designator C?  ValueDisplayed: 0.1µF  (hidden comment: 08055C104KAT2A)
CAP, CERM, 0.1 µF, 50 V,+/- 10%, X7R, 0805; Manufacturer: AVX; Polarized: N; CompType: Capacitor; Value: 0.1uF; U/M: EA; Cap_F: 0.0000001; Tolerance_%: 10; ESR_ohm: 0.024; Value1: 0.024 ohm; VDC_V: 50; Value2: 50V; TaMin_C: -55; TaMax_C: 125; Cap_Case: 0805; SizeArea_mm2: 2.5; SizeAreaWB_mm2: 6.75; SizeX_mm: 2; SizeY_mm: 1.25; SizeZ_mm: 1.45; AEC Category: Q200; Green_Lifecycle: Active; Green_REACh: Passed
signal-integrity model Cap
simulation model Cap
footprint 0805_HV
footprint 0805_HV1
footprint 0805
footprint 0805M
footprint 0805L
pins: 1, 2

## 08055C104MAT2A
designator C?  ValueDisplayed: 0.1µF  (hidden comment: 08055C104MAT2A)
CAP, CERM, 0.1 µF, 50 V,+/- 20%, X7R, 0805; Manufacturer: AVX; Polarized: N; CompType: Capacitor; Value: 0.1uF; U/M: EA; Cap_F: 0.0000001; Tolerance_%: 20; ESR_ohm: 0.024; Value1: 0.024 ohm; VDC_V: 50; Value2: 50V; TaMin_C: -55; TaMax_C: 125; Cap_Case: 0805; SizeArea_mm2: 2.5; SizeAreaWB_mm2: 6.75; SizeX_mm: 2; SizeY_mm: 1.25; SizeZ_mm: 1.45; AEC Category: Q200; Green_Lifecycle: Active; Green_REACh: Passed
signal-integrity model Cap
simulation model Cap
footprint 0805_HV
footprint 0805_HV1
footprint 0805
footprint 0805M
footprint 0805L
pins: 1, 2

## 08055C105KAT2A
designator C?  ValueDisplayed: 1µF  (hidden comment: 08055C105KAT2A)
CAP, CERM, 1 µF, 50 V,+/- 10%, X7R, 0805; Manufacturer: AVX; Polarized: N; CompType: Capacitor; Value: 1uF; U/M: EA; Cap_F: 0.000001; Tolerance_%: 10; VDC_V: 50; Value2: 50V; TaMin_C: -55; TaMax_C: 125; Cap_Case: 0805; SizeArea_mm2: 2.5; SizeAreaWB_mm2: 6.75; SizeX_mm: 2; SizeY_mm: 1.25; SizeZ_mm: 1.45; AEC Category: Q200; Green_Lifecycle: Active; Green_REACh: Passed
signal-integrity model Cap
simulation model Cap
footprint 0805_HV
footprint 0805_HV1
footprint 0805
footprint 0805M
footprint 0805L
pins: 1, 2

## 08055C122KAT2A
designator C?  ValueDisplayed: 1200pF  (hidden comment: 08055C122KAT2A)
CAP, CERM, 1200 pF, 50 V,+/- 10%, X7R, 0805; Manufacturer: AVX; Polarized: N; CompType: Capacitor; Value: 1200pF; U/M: EA; Cap_F: 0.0000000012; Tolerance_%: 10; ESR_ohm: 0.261; Value1: 0.261 ohm; VDC_V: 50; Value2: 50V; TaMin_C: -55; TaMax_C: 125; Cap_Case: 0805; SizeArea_mm2: 2.5; SizeAreaWB_mm2: 6.75; SizeX_mm: 2; SizeY_mm: 1.25; SizeZ_mm: 1.45; AEC Category: Q200; Green_Lifecycle: Active; Green_REACh: Passed
signal-integrity model Cap
simulation model Cap
footprint 0805_HV
footprint 0805_HV1
footprint 0805
footprint 0805M
footprint 0805L
pins: 1, 2

## 08055C123KAT2A
designator C?  ValueDisplayed: 0.012µF  (hidden comment: 08055C123KAT2A)
CAP, CERM, 0.012 µF, 50 V,+/- 10%, X7R, 0805; Manufacturer: AVX; Polarized: N; CompType: Capacitor; Value: 0.012uF; U/M: EA; Cap_F: 0.000000012; Tolerance_%: 10; ESR_ohm: 0.071; Value1: 0.071 ohm; VDC_V: 50; Value2: 50V; TaMin_C: -55; TaMax_C: 125; Cap_Case: 0805; SizeArea_mm2: 2.5; SizeAreaWB_mm2: 6.75; SizeX_mm: 2; SizeY_mm: 1.25; SizeZ_mm: 1.45; AEC Category: Q200; Green_Lifecycle: Active; Green_REACh: Passed
signal-integrity model Cap
simulation model Cap
footprint 0805_HV
footprint 0805_HV1
footprint 0805
footprint 0805M
footprint 0805L
pins: 1, 2

## 08055C124KAT2A
designator C?  ValueDisplayed: 0.12µF  (hidden comment: 08055C124KAT2A)
CAP, CERM, 0.12 µF, 50 V,+/- 10%, X7R, 0805; Manufacturer: AVX; Polarized: N; CompType: Capacitor; Value: 0.12uF; U/M: EA; Cap_F: 0.00000012; Tolerance_%: 10; ESR_ohm: 0.022; Value1: 0.022 ohm; VDC_V: 50; Value2: 50V; TaMin_C: -55; TaMax_C: 125; Cap_Case: 0805; SizeArea_mm2: 2.5; SizeAreaWB_mm2: 6.75; SizeX_mm: 2; SizeY_mm: 1.25; SizeZ_mm: 1.45; AEC Category: Q200; Green_Lifecycle: Not Set; Green_REACh: Incomplete
signal-integrity model Cap
simulation model Cap
footprint 0805_HV
footprint 0805_HV1
footprint 0805
footprint 0805M
footprint 0805L
pins: 1, 2

## 08055C152KAT2A
designator C?  ValueDisplayed: 1500pF  (hidden comment: 08055C152KAT2A)
CAP, CERM, 1500 pF, 50 V,+/- 10%, X7R, 0805; Manufacturer: AVX; Polarized: N; CompType: Capacitor; Value: 1500pF; U/M: EA; Cap_F: 0.0000000015; Tolerance_%: 10; ESR_ohm: 0.229; Value1: 0.229 ohm; VDC_V: 50; Value2: 50V; TaMin_C: -55; TaMax_C: 125; Cap_Case: 0805; SizeArea_mm2: 2.5; SizeAreaWB_mm2: 6.75; SizeX_mm: 2; SizeY_mm: 1.25; SizeZ_mm: 1.45; AEC Category: Q200; Green_Lifecycle: Not Set; Green_REACh: Incomplete
signal-integrity model Cap
simulation model Cap
footprint 0805_HV
footprint 0805_HV1
footprint 0805
footprint 0805M
footprint 0805L
pins: 1, 2

## 08055C153KAT2A
designator C?  ValueDisplayed: 0.015µF  (hidden comment: 08055C153KAT2A)
CAP, CERM, 0.015 µF, 50 V,+/- 10%, X7R, 0805; Manufacturer: AVX; Polarized: N; CompType: Capacitor; Value: 0.015uF; U/M: EA; Cap_F: 0.000000015; Tolerance_%: 10; ESR_ohm: 0.063; Value1: 0.063 ohm; VDC_V: 50; Value2: 50V; TaMin_C: -55; TaMax_C: 125; Cap_Case: 0805; SizeArea_mm2: 2.5; SizeAreaWB_mm2: 6.75; SizeX_mm: 2; SizeY_mm: 1.25; SizeZ_mm: 1.45; AEC Category: Q200; Green_Lifecycle: Not Set; Green_REACh: Incomplete
signal-integrity model Cap
simulation model Cap
footprint 0805_HV
footprint 0805_HV1
footprint 0805
footprint 0805M
footprint 0805L
pins: 1, 2

## 08055C182KAT2A
designator C?  ValueDisplayed: 1800pF  (hidden comment: 08055C182KAT2A)
CAP, CERM, 1800 pF, 50 V,+/- 10%, X7R, 0805; Manufacturer: AVX; Polarized: N; CompType: Capacitor; Value: 1800pF; U/M: EA; Cap_F: 0.0000000018; Tolerance_%: 10; ESR_ohm: 0.206; Value1: 0.206 ohm; VDC_V: 50; Value2: 50V; TaMin_C: -55; TaMax_C: 125; Cap_Case: 0805; SizeArea_mm2: 2.5; SizeAreaWB_mm2: 6.75; SizeX_mm: 2; SizeY_mm: 1.25; SizeZ_mm: 1.45; AEC Category: Q200; Green_Lifecycle: Not Set; Green_REACh: Incomplete
signal-integrity model Cap
simulation model Cap
footprint 0805_HV
footprint 0805_HV1
footprint 0805
footprint 0805M
footprint 0805L
pins: 1, 2

## 08055C183KAT2A
designator C?  ValueDisplayed: 0.018µF  (hidden comment: 08055C183KAT2A)
CAP, CERM, 0.018 µF, 50 V,+/- 10%, X7R, 0805; Manufacturer: AVX; Polarized: N; CompType: Capacitor; Value: 0.018uF; U/M: EA; Cap_F: 0.000000018; Tolerance_%: 10; ESR_ohm: 0.058; Value1: 0.058 ohm; VDC_V: 50; Value2: 50V; TaMin_C: -55; TaMax_C: 125; Cap_Case: 0805; SizeArea_mm2: 2.5; SizeAreaWB_mm2: 6.75; SizeX_mm: 2; SizeY_mm: 1.25; SizeZ_mm: 1.45; AEC Category: Q200; Green_Lifecycle: Not Set; Green_REACh: Incomplete
signal-integrity model Cap
simulation model Cap
footprint 0805_HV
footprint 0805_HV1
footprint 0805
footprint 0805M
footprint 0805L
pins: 1, 2

## 08055C221KAT2A
designator C?  ValueDisplayed: 220pF  (hidden comment: 08055C221KAT2A)
CAP, CERM, 220 pF, 50 V,+/- 10%, X7R, 0805; Manufacturer: AVX; Polarized: N; CompType: Capacitor; Value: 220pF; U/M: EA; Cap_F: 0.00000000022; Tolerance_%: 10; ESR_ohm: 0.724; Value1: 0.724 ohm; VDC_V: 50; Value2: 50V; TaMin_C: -55; TaMax_C: 125; Cap_Case: 0805; SizeArea_mm2: 2.5; SizeAreaWB_mm2: 6.75; SizeX_mm: 2; SizeY_mm: 1.25; SizeZ_mm: 1.45; AEC Category: Q200; Green_Lifecycle: Not Set; Green_REACh: Incomplete
signal-integrity model Cap
simulation model Cap
footprint 0805_HV
footprint 0805_HV1
footprint 0805
footprint 0805M
footprint 0805L
pins: 1, 2

## 08055C222KAT2A
designator C?  ValueDisplayed: 2200pF  (hidden comment: 08055C222KAT2A)
CAP, CERM, 2200 pF, 50 V,+/- 10%, X7R, 0805; Manufacturer: AVX; Polarized: N; CompType: Capacitor; Value: 2200pF; U/M: EA; Cap_F: 0.0000000022; Tolerance_%: 10; ESR_ohm: 0.183; Value1: 0.183 ohm; VDC_V: 50; Value2: 50V; TaMin_C: -55; TaMax_C: 125; Cap_Case: 0805; SizeArea_mm2: 2.5; SizeAreaWB_mm2: 6.75; SizeX_mm: 2; SizeY_mm: 1.25; SizeZ_mm: 1.45; AEC Category: Q200; Green_Lifecycle: Active; Green_REACh: Passed
signal-integrity model Cap
simulation model Cap
footprint 0805_HV
footprint 0805_HV1
footprint 0805
footprint 0805M
footprint 0805L
pins: 1, 2

## 08055C223KAT2A
designator C?  ValueDisplayed: 0.022µF  (hidden comment: 08055C223KAT2A)
CAP, CERM, 0.022 µF, 50 V,+/- 10%, X7R, 0805; Manufacturer: AVX; Polarized: N; CompType: Capacitor; Value: 0.022uF; U/M: EA; Cap_F: 0.000000022; Tolerance_%: 10; ESR_ohm: 0.052; Value1: 0.052 ohm; VDC_V: 50; Value2: 50V; TaMin_C: -55; TaMax_C: 125; Cap_Case: 0805; SizeArea_mm2: 2.5; SizeAreaWB_mm2: 6.75; SizeX_mm: 2; SizeY_mm: 1.25; SizeZ_mm: 1.45; AEC Category: Q200; Green_Lifecycle: Not Set; Green_REACh: Incomplete
signal-integrity model Cap
simulation model Cap
footprint 0805_HV
footprint 0805_HV1
footprint 0805
footprint 0805M
footprint 0805L
pins: 1, 2

## 08055C271KAT2A
designator C?  ValueDisplayed: 270pF  (hidden comment: 08055C271KAT2A)
CAP, CERM, 270 pF, 50 V,+/- 10%, X7R, 0805; Manufacturer: AVX; Polarized: N; CompType: Capacitor; Value: 270pF; U/M: EA; Cap_F: 0.00000000027; Tolerance_%: 10; ESR_ohm: 0.637; Value1: 0.637 ohm; VDC_V: 50; Value2: 50V; TaMin_C: -55; TaMax_C: 125; Cap_Case: 0805; SizeArea_mm2: 2.5; SizeAreaWB_mm2: 6.75; SizeX_mm: 2; SizeY_mm: 1.25; SizeZ_mm: 1.45; AEC Category: Q200; Green_Lifecycle: Active; Green_REACh: Passed
signal-integrity model Cap
simulation model Cap
footprint 0805_HV
footprint 0805_HV1
footprint 0805
footprint 0805M
footprint 0805L
pins: 1, 2

## 08055C272KAT2A
designator C?  ValueDisplayed: 2700pF  (hidden comment: 08055C272KAT2A)
CAP, CERM, 2700 pF, 50 V,+/- 10%, X7R, 0805; Manufacturer: AVX; Polarized: N; CompType: Capacitor; Value: 2700pF; U/M: EA; Cap_F: 0.0000000027; Tolerance_%: 10; ESR_ohm: 0.163; Value1: 0.163 ohm; VDC_V: 50; Value2: 50V; TaMin_C: -55; TaMax_C: 125; Cap_Case: 0805; SizeArea_mm2: 2.5; SizeAreaWB_mm2: 6.75; SizeX_mm: 2; SizeY_mm: 1.25; SizeZ_mm: 1.45; AEC Category: Q200; Green_Lifecycle: Not Set; Green_REACh: Incomplete
signal-integrity model Cap
simulation model Cap
footprint 0805_HV
footprint 0805_HV1
footprint 0805
footprint 0805M
footprint 0805L
pins: 1, 2

## 08055C273KAT2A
designator C?  ValueDisplayed: 0.027µF  (hidden comment: 08055C273KAT2A)
CAP, CERM, 0.027 µF, 50 V,+/- 10%, X7R, 0805; Manufacturer: AVX; Polarized: N; CompType: Capacitor; Value: 0.027uF; U/M: EA; Cap_F: 0.000000027; Tolerance_%: 10; ESR_ohm: 0.047; Value1: 0.047 ohm; VDC_V: 50; Value2: 50V; TaMin_C: -55; TaMax_C: 125; Cap_Case: 0805; SizeArea_mm2: 2.5; SizeAreaWB_mm2: 6.75; SizeX_mm: 2; SizeY_mm: 1.25; SizeZ_mm: 1.45; AEC Category: Q200; Green_Lifecycle: Active; Green_REACh: Passed
signal-integrity model Cap
simulation model Cap
footprint 0805_HV
footprint 0805_HV1
footprint 0805
footprint 0805M
footprint 0805L
pins: 1, 2

## 08055C331KAT2A
designator C?  ValueDisplayed: 330pF  (hidden comment: 08055C331KAT2A)
CAP, CERM, 330 pF, 50 V,+/- 10%, X7R, 0805; Manufacturer: AVX; Polarized: N; CompType: Capacitor; Value: 330pF; U/M: EA; Cap_F: 0.00000000033; Tolerance_%: 10; ESR_ohm: 0.563; Value1: 0.563 ohm; VDC_V: 50; Value2: 50V; TaMin_C: -55; TaMax_C: 125; Cap_Case: 0805; SizeArea_mm2: 2.5; SizeAreaWB_mm2: 6.75; SizeX_mm: 2; SizeY_mm: 1.25; SizeZ_mm: 1.45; AEC Category: Q200; Green_Lifecycle: Active; Green_REACh: Passed
signal-integrity model Cap
simulation model Cap
footprint 0805_HV
footprint 0805_HV1
footprint 0805
footprint 0805M
footprint 0805L
pins: 1, 2

## 08055C332KAT2A
designator C?  ValueDisplayed: 3300pF  (hidden comment: 08055C332KAT2A)
CAP, CERM, 3300 pF, 50 V,+/- 10%, X7R, 0805; Manufacturer: AVX; Polarized: N; CompType: Capacitor; Value: 3300pF; U/M: EA; Cap_F: 0.0000000033; Tolerance_%: 10; ESR_ohm: 0.145; Value1: 0.145 ohm; VDC_V: 50; Value2: 50V; TaMin_C: -55; TaMax_C: 125; Cap_Case: 0805; SizeArea_mm2: 2.5; SizeAreaWB_mm2: 6.75; SizeX_mm: 2; SizeY_mm: 1.25; SizeZ_mm: 1.45; AEC Category: Q200; Green_Lifecycle: Not Set; Green_REACh: Incomplete
signal-integrity model Cap
simulation model Cap
footprint 0805_HV
footprint 0805_HV1
footprint 0805
footprint 0805M
footprint 0805L
pins: 1, 2

## 08055C333JAT2A
designator C?  ValueDisplayed: 0.033µF  (hidden comment: 08055C333JAT2A)
CAP, CERM, 0.033 µF, 50 V,+/- 5%, X7R, 0805; Manufacturer: AVX; Polarized: N; CompType: Capacitor; Value: 0.033uF; U/M: EA; Cap_F: 0.000000033; Tolerance_%: 5; ESR_ohm: 0.042; Value1: 0.042 ohm; VDC_V: 50; Value2: 50V; TaMin_C: -55; TaMax_C: 125; Cap_Case: 0805; SizeArea_mm2: 2.5; SizeAreaWB_mm2: 6.75; SizeX_mm: 2; SizeY_mm: 1.25; SizeZ_mm: 1.45; AEC Category: Q200; Green_Lifecycle: Not Set; Green_REACh: Incomplete
signal-integrity model Cap
simulation model Cap
footprint 0805_HV
footprint 0805_HV1
footprint 0805
footprint 0805M
footprint 0805L
pins: 1, 2

## 08055C333KAT2A
designator C?  ValueDisplayed: 0.033µF  (hidden comment: 08055C333KAT2A)
CAP, CERM, 0.033 µF, 50 V,+/- 10%, X7R, 0805; Manufacturer: AVX; Polarized: N; CompType: Capacitor; Value: 0.033uF; U/M: EA; Cap_F: 0.000000033; Tolerance_%: 10; ESR_ohm: 0.042; Value1: 0.042 ohm; VDC_V: 50; Value2: 50V; TaMin_C: -55; TaMax_C: 125; Cap_Case: 0805; SizeArea_mm2: 2.5; SizeAreaWB_mm2: 6.75; SizeX_mm: 2; SizeY_mm: 1.25; SizeZ_mm: 1.45; AEC Category: Q200; Green_Lifecycle: Not Set; Green_REACh: Incomplete
signal-integrity model Cap
simulation model Cap
footprint 0805_HV
footprint 0805_HV1
footprint 0805
footprint 0805M
footprint 0805L
pins: 1, 2

## 08055C391KAT2A
designator C?  ValueDisplayed: 390pF  (hidden comment: 08055C391KAT2A)
CAP, CERM, 390 pF, 50 V,+/- 10%, X7R, 0805; Manufacturer: AVX; Polarized: N; CompType: Capacitor; Value: 390pF; U/M: EA; Cap_F: 0.00000000039; Tolerance_%: 10; ESR_ohm: 0.509; Value1: 0.509 ohm; VDC_V: 50; Value2: 50V; TaMin_C: -55; TaMax_C: 125; Cap_Case: 0805; SizeArea_mm2: 2.5; SizeAreaWB_mm2: 6.75; SizeX_mm: 2; SizeY_mm: 1.25; SizeZ_mm: 1.45; AEC Category: Q200; Green_Lifecycle: Not Set; Green_REACh: Incomplete
signal-integrity model Cap
simulation model Cap
footprint 0805_HV
footprint 0805_HV1
footprint 0805
footprint 0805M
footprint 0805L
pins: 1, 2

## 08055C392KAT2A
designator C?  ValueDisplayed: 3900pF  (hidden comment: 08055C392KAT2A)
CAP, CERM, 3900 pF, 50 V,+/- 10%, X7R, 0805; Manufacturer: AVX; Polarized: N; CompType: Capacitor; Value: 3900pF; U/M: EA; Cap_F: 0.0000000039; Tolerance_%: 10; ESR_ohm: 0.132; Value1: 0.132 ohm; VDC_V: 50; Value2: 50V; TaMin_C: -55; TaMax_C: 125; Cap_Case: 0805; SizeArea_mm2: 2.5; SizeAreaWB_mm2: 6.75; SizeX_mm: 2; SizeY_mm: 1.25; SizeZ_mm: 1.45; AEC Category: Q200; Green_Lifecycle: Not Set; Green_REACh: Incomplete
signal-integrity model Cap
simulation model Cap
footprint 0805_HV
footprint 0805_HV1
footprint 0805
footprint 0805M
footprint 0805L
pins: 1, 2

## 08055C393KAT2A
designator C?  ValueDisplayed: 0.039µF  (hidden comment: 08055C393KAT2A)
CAP, CERM, 0.039 µF, 50 V,+/- 10%, X7R, 0805; Manufacturer: AVX; Polarized: N; CompType: Capacitor; Value: 0.039uF; U/M: EA; Cap_F: 0.000000039; Tolerance_%: 10; ESR_ohm: 0.038; Value1: 0.038 ohm; VDC_V: 50; Value2: 50V; TaMin_C: -55; TaMax_C: 125; Cap_Case: 0805; SizeArea_mm2: 2.5; SizeAreaWB_mm2: 6.75; SizeX_mm: 2; SizeY_mm: 1.25; SizeZ_mm: 1.45; AEC Category: Q200; Green_Lifecycle: Not Set; Green_REACh: Incomplete
signal-integrity model Cap
simulation model Cap
footprint 0805_HV
footprint 0805_HV1
footprint 0805
footprint 0805M
footprint 0805L
pins: 1, 2

## 08055C471KAT2A
designator C?  ValueDisplayed: 470pF  (hidden comment: 08055C471KAT2A)
CAP, CERM, 470 pF, 50 V,+/- 10%, X7R, 0805; Manufacturer: AVX; Polarized: N; CompType: Capacitor; Value: 470pF; U/M: EA; Cap_F: 0.00000000047; Tolerance_%: 10; ESR_ohm: 0.454; Value1: 0.454 ohm; VDC_V: 50; Value2: 50V; TaMin_C: -55; TaMax_C: 125; Cap_Case: 0805; SizeArea_mm2: 2.5; SizeAreaWB_mm2: 6.75; SizeX_mm: 2; SizeY_mm: 1.25; SizeZ_mm: 1.45; AEC Category: Q200; Green_Lifecycle: Not Set; Green_REACh: Incomplete
signal-integrity model Cap
simulation model Cap
footprint 0805_HV
footprint 0805_HV1
footprint 0805
footprint 0805M
footprint 0805L
pins: 1, 2

## 08055C472JAT2A
designator C?  ValueDisplayed: 4700pF  (hidden comment: 08055C472JAT2A)
CAP, CERM, 4700 pF, 50 V,+/- 5%, X7R, 0805; Manufacturer: AVX; Polarized: N; CompType: Capacitor; Value: 4700pF; U/M: EA; Cap_F: 0.0000000047; Tolerance_%: 5; ESR_ohm: 0.119; Value1: 0.119 ohm; VDC_V: 50; Value2: 50V; TaMin_C: -55; TaMax_C: 125; Cap_Case: 0805; SizeArea_mm2: 2.5; SizeAreaWB_mm2: 6.75; SizeX_mm: 2; SizeY_mm: 1.25; SizeZ_mm: 1.45; AEC Category: Q200; Green_Lifecycle: Active; Green_REACh: Passed
signal-integrity model Cap
simulation model Cap
footprint 0805_HV
footprint 0805_HV1
footprint 0805
footprint 0805M
footprint 0805L
pins: 1, 2

## 08055C472KAT2A
designator C?  ValueDisplayed: 4700pF  (hidden comment: 08055C472KAT2A)
CAP, CERM, 4700 pF, 50 V,+/- 10%, X7R, 0805; Manufacturer: AVX; Polarized: N; CompType: Capacitor; Value: 4700pF; U/M: EA; Cap_F: 0.0000000047; Tolerance_%: 10; ESR_ohm: 0.119; Value1: 0.119 ohm; VDC_V: 50; Value2: 50V; TaMin_C: -55; TaMax_C: 125; Cap_Case: 0805; SizeArea_mm2: 2.5; SizeAreaWB_mm2: 6.75; SizeX_mm: 2; SizeY_mm: 1.25; SizeZ_mm: 1.45; AEC Category: Q200; Green_Lifecycle: Active; Green_REACh: Passed
signal-integrity model Cap
simulation model Cap
footprint 0805_HV
footprint 0805_HV1
footprint 0805
footprint 0805M
footprint 0805L
pins: 1, 2

## 08055C473JAT2A
designator C?  ValueDisplayed: 0.047µF  (hidden comment: 08055C473JAT2A)
CAP, CERM, 0.047 µF, 50 V,+/- 5%, X7R, 0805; Manufacturer: AVX; Polarized: N; CompType: Capacitor; Value: 0.047uF; U/M: EA; Cap_F: 0.000000047; Tolerance_%: 5; ESR_ohm: 0.035; Value1: 0.035 ohm; VDC_V: 50; Value2: 50V; TaMin_C: -55; TaMax_C: 125; Cap_Case: 0805; SizeArea_mm2: 2.5; SizeAreaWB_mm2: 6.75; SizeX_mm: 2; SizeY_mm: 1.25; SizeZ_mm: 1.45; AEC Category: Q200; Green_Lifecycle: Active; Green_REACh: Passed
signal-integrity model Cap
simulation model Cap
footprint 0805_HV
footprint 0805_HV1
footprint 0805
footprint 0805M
footprint 0805L
pins: 1, 2

## 08055C473KAT2A
designator C?  ValueDisplayed: 0.047µF  (hidden comment: 08055C473KAT2A)
CAP, CERM, 0.047 µF, 50 V,+/- 10%, X7R, 0805; Manufacturer: AVX; Polarized: N; CompType: Capacitor; Value: 0.047uF; U/M: EA; Cap_F: 0.000000047; Tolerance_%: 10; ESR_ohm: 0.035; Value1: 0.035 ohm; VDC_V: 50; Value2: 50V; TaMin_C: -55; TaMax_C: 125; Cap_Case: 0805; SizeArea_mm2: 2.5; SizeAreaWB_mm2: 6.75; SizeX_mm: 2; SizeY_mm: 1.25; SizeZ_mm: 1.45; AEC Category: Q200; Green_Lifecycle: Active; Green_REACh: Passed
signal-integrity model Cap
simulation model Cap
footprint 0805_HV
footprint 0805_HV1
footprint 0805
footprint 0805M
footprint 0805L
pins: 1, 2

## 08055C561KAT2A
designator C?  ValueDisplayed: 560pF  (hidden comment: 08055C561KAT2A)
CAP, CERM, 560 pF, 50 V,+/- 10%, X7R, 0805; Manufacturer: AVX; Polarized: N; CompType: Capacitor; Value: 560pF; U/M: EA; Cap_F: 0.00000000056; Tolerance_%: 10; ESR_ohm: 0.409; Value1: 0.409 ohm; VDC_V: 50; Value2: 50V; TaMin_C: -55; TaMax_C: 125; Cap_Case: 0805; SizeArea_mm2: 2.5; SizeAreaWB_mm2: 6.75; SizeX_mm: 2; SizeY_mm: 1.25; SizeZ_mm: 1.45; AEC Category: Q200; Green_Lifecycle: Not Set; Green_REACh: Incomplete
signal-integrity model Cap
simulation model Cap
footprint 0805_HV
footprint 0805_HV1
footprint 0805
footprint 0805M
footprint 0805L
pins: 1, 2

## 08055C562KAT2A
designator C?  ValueDisplayed: 5600pF  (hidden comment: 08055C562KAT2A)
CAP, CERM, 5600 pF, 50 V,+/- 10%, X7R, 0805; Manufacturer: AVX; Polarized: N; CompType: Capacitor; Value: 5600pF; U/M: EA; Cap_F: 0.0000000056; Tolerance_%: 10; ESR_ohm: 0.107; Value1: 0.107 ohm; VDC_V: 50; Value2: 50V; TaMin_C: -55; TaMax_C: 125; Cap_Case: 0805; SizeArea_mm2: 2.5; SizeAreaWB_mm2: 6.75; SizeX_mm: 2; SizeY_mm: 1.25; SizeZ_mm: 1.45; AEC Category: Q200; Green_Lifecycle: Not Set; Green_REACh: Incomplete
signal-integrity model Cap
simulation model Cap
footprint 0805_HV
footprint 0805_HV1
footprint 0805
footprint 0805M
footprint 0805L
pins: 1, 2

## 08055C563KAT2A
designator C?  ValueDisplayed: 0.056µF  (hidden comment: 08055C563KAT2A)
CAP, CERM, 0.056 µF, 50 V,+/- 10%, X7R, 0805; Manufacturer: AVX; Polarized: N; CompType: Capacitor; Value: 0.056uF; U/M: EA; Cap_F: 0.000000056; Tolerance_%: 10; ESR_ohm: 0.032; Value1: 0.032 ohm; VDC_V: 50; Value2: 50V; TaMin_C: -55; TaMax_C: 125; Cap_Case: 0805; SizeArea_mm2: 2.5; SizeAreaWB_mm2: 6.75; SizeX_mm: 2; SizeY_mm: 1.25; SizeZ_mm: 1.45; AEC Category: Q200; Green_Lifecycle: Not Set; Green_REACh: Incomplete
signal-integrity model Cap
simulation model Cap
footprint 0805_HV
footprint 0805_HV1
footprint 0805
footprint 0805M
footprint 0805L
pins: 1, 2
